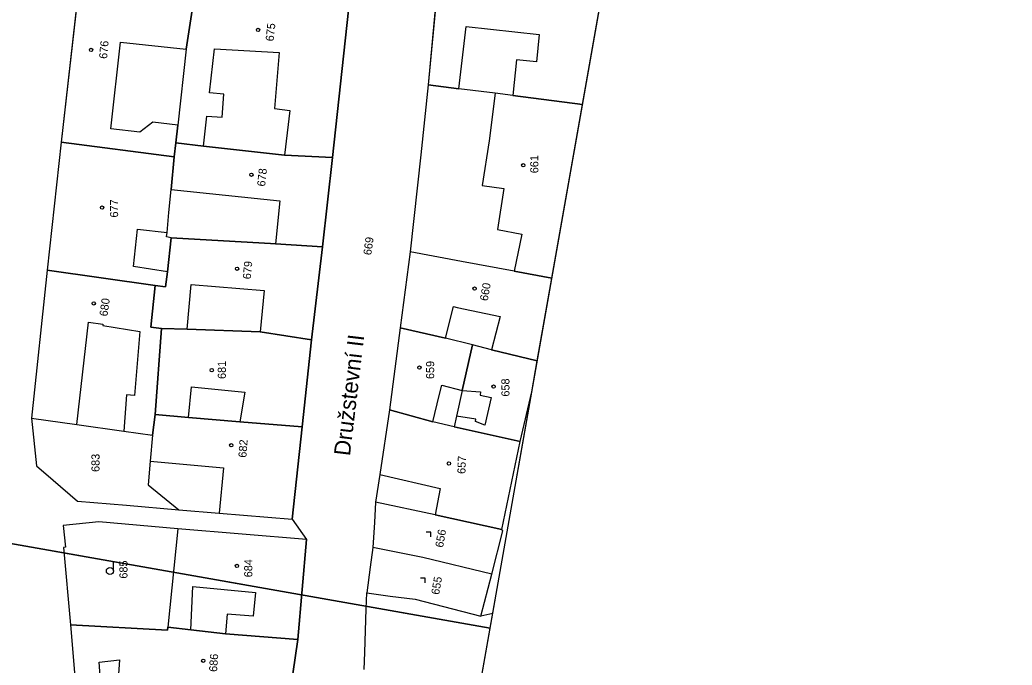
# Model space of a CAD drawing. Extents: x -534481 to -534262, y -1190577 to -1190138.
# Drawn here: x -534365.7 to -534261.7, y -1190477.6 to -1190410 of the extents above; entities that cross this region are included whole.
import ezdxf

# ---------------------------------------------------------------- set-up
doc = ezdxf.new("R2010")
doc.units = 0
for name, color, linetype in [('Definiční body', 7, 'Continuous'), ('Polygon budovy', 7, 'Continuous'), ('Polygon parcely', 7, 'Continuous'), ('Vrstva 30', 7, 'Continuous'), ('Vrstva 43', 7, 'Continuous'), ('Vrstva 46', 7, 'Continuous'), ('Vrstva 47', 7, 'Continuous'), ('Vrstva 48', 7, 'Continuous')]:
    doc.layers.add(name, color=color, linetype=linetype)

msp = doc.modelspace()

# ---------------------------------------------------------------- linework, layer by layer
at = {"layer": 'Definiční body'}
for p, q in [((-534321.81, -1190405.38), (-534322.86, -1190416.77)), ((-534359.48, -1190406.45), (-534361.32, -1190422.75)), ((-534331.23, -1190408.93), (-534332.91, -1190424.36)), ((-534361.32, -1190422.75), (-534362.8, -1190436.16)), ((-534361.32, -1190422.75), (-534349.49, -1190424.31)), ((-534349.49, -1190424.31), (-534349.31, -1190422.85)), ((-534332.91, -1190424.36), (-534333.96, -1190433.74)), ((-534333.96, -1190433.74), (-534335.08, -1190443.48)), ((-534324.75, -1190434.26), (-534325.81, -1190442.2)), ((-534362.8, -1190436.16), (-534364.44, -1190451.69)), ((-534362.8, -1190436.16), (-534351.49, -1190437.77)), ((-534351.49, -1190451.29), (-534350.82, -1190442.28)), ((-534325.81, -1190442.2), (-534326.91, -1190450.79)), ((-534335.08, -1190443.48), (-534336.06, -1190452.6)), ((-534313.23, -1190454.11), (-534312, -1190448.93)), ((-534351.77, -1190453.45), (-534351.49, -1190451.29)), ((-534336.06, -1190452.6), (-534337.13, -1190462.26)), ((-534313.23, -1190454.11), (-534320.15, -1190452.59)), ((-534351.77, -1190453.45), (-534351.99, -1190456.19)), ((-534315.15, -1190463.36), (-534313.23, -1190454.11)), ((-534337.13, -1190462.26), (-534335.61, -1190464.4)), ((-534349.11, -1190463.29), (-534350.15, -1190473.56)), ((-534335.61, -1190464.4), (-534349.11, -1190463.29)), ((-534335.61, -1190464.4), (-534336.54, -1190474.87)), ((-534317.36, -1190472.42), (-534316.19, -1190468.02)), ((-534360.35, -1190473.34), (-534359.92, -1190478.31))]:
    msp.add_line(p, q, dxfattribs=at)
for points in [[(-534347.45, -1190408.02), (-534348.24, -1190413.03), (-534349.11, -1190420.99), (-534349.31, -1190422.85)], [(-534322.86, -1190416.77), (-534323.65, -1190424.09), (-534324.75, -1190434.26)], [(-534306.7, -1190418.82), (-534314.01, -1190417.87), (-534315.84, -1190417.64), (-534319.66, -1190417.17), (-534322.86, -1190416.77)], [(-534349.31, -1190422.85), (-534346.43, -1190423.17), (-534337.91, -1190424.11), (-534332.91, -1190424.36)], [(-534349.79, -1190432.77), (-534350.28, -1190432.67), (-534350.24, -1190432.22), (-534350.04, -1190430.15), (-534349.82, -1190427.74), (-534349.49, -1190424.31)], [(-534351.49, -1190437.77), (-534350.38, -1190437.91), (-534350.2, -1190436.34), (-534349.79, -1190432.77)], [(-534349.79, -1190432.77), (-534345.53, -1190433.02), (-534339.38, -1190433.37), (-534338.88, -1190433.41), (-534333.96, -1190433.74)], [(-534309.9, -1190437), (-534313.86, -1190436.27), (-534319.38, -1190435.25), (-534324.75, -1190434.26)], [(-534351.49, -1190437.77), (-534351.94, -1190442.14), (-534350.82, -1190442.28)], [(-534350.82, -1190442.28), (-534348.14, -1190442.37), (-534340.49, -1190442.65), (-534335.08, -1190443.48)], [(-534318.21, -1190444.01), (-534321.04, -1190443.31), (-534325.81, -1190442.2)], [(-534318.21, -1190444.01), (-534319.29, -1190448.78), (-534319.9, -1190451.46), (-534320.15, -1190452.59)], [(-534311.43, -1190445.66), (-534316.23, -1190444.51), (-534318.21, -1190444.01)], [(-534326.91, -1190450.79), (-534327.94, -1190457.58), (-534328.38, -1190460.47)], [(-534320.15, -1190452.59), (-534322.37, -1190452.05), (-534326.91, -1190450.79)], [(-534364.44, -1190451.69), (-534363.92, -1190456.68), (-534362.18, -1190458.17), (-534359.62, -1190460.37), (-534354.49, -1190460.81), (-534349.01, -1190461.28)], [(-534364.44, -1190451.69), (-534359.68, -1190452.35), (-534354.78, -1190453.03), (-534351.77, -1190453.45)], [(-534351.49, -1190451.29), (-534348, -1190451.6), (-534342.6, -1190452.08), (-534336.06, -1190452.6)], [(-534351.99, -1190456.19), (-534352.2, -1190458.68), (-534349.01, -1190461.28)], [(-534349.01, -1190461.28), (-534344.78, -1190461.63), (-534337.13, -1190462.26)], [(-534328.38, -1190460.47), (-534328.51, -1190462.62), (-534328.68, -1190465.22)], [(-534315.15, -1190463.36), (-534322.12, -1190461.79), (-534328.38, -1190460.47)], [(-534349.11, -1190463.29), (-534357.38, -1190462.53), (-534361.12, -1190462.94), (-534360.89, -1190465.2), (-534361.07, -1190465.23), (-534360.35, -1190473.34)], [(-534316.19, -1190468.02), (-534315.05, -1190463.47), (-534315.15, -1190463.36)], [(-534328.68, -1190465.22), (-534328.95, -1190467.29), (-534329.3, -1190469.99)], [(-534316.19, -1190468.02), (-534323.42, -1190466.26), (-534328.68, -1190465.22)], [(-534329.58, -1190478.02), (-534329.52, -1190476.22), (-534329.36, -1190471.67), (-534329.3, -1190469.99)], [(-534329.3, -1190469.99), (-534326.86, -1190470.31), (-534324.23, -1190470.65), (-534317.36, -1190472.42)], [(-534316.1, -1190472.16), (-534317.36, -1190472.42)], [(-534360.35, -1190473.34), (-534350.19, -1190473.9), (-534350.15, -1190473.56)], [(-534350.15, -1190473.56), (-534347.75, -1190473.84), (-534344.1, -1190474.27), (-534336.54, -1190474.87)], [(-534336.54, -1190474.87), (-534337.79, -1190483.49), (-534339.53, -1190483.31)]]:
    msp.add_lwpolyline(points, dxfattribs=at)
at = {"layer": 'Polygon parcely'}
for p, q in [((-534306.7, -1190418.82), (-534304.95, -1190408.92)), ((-534309.9, -1190437), (-534306.7, -1190418.82)), ((-534311.43, -1190445.66), (-534309.9, -1190437)), ((-534312, -1190448.93), (-534311.43, -1190445.66))]:
    msp.add_line(p, q, dxfattribs=at)
for points in [[(-534304.95, -1190408.92), (-534304.7, -1190406.9), (-534310.69, -1190406.47), (-534319.12, -1190405.49), (-534321.81, -1190405.38), (-534322.86, -1190416.77), (-534319.66, -1190417.17), (-534318.89, -1190410.64), (-534311.23, -1190411.47), (-534311.53, -1190414.36), (-534313.6, -1190414.13), (-534314.01, -1190417.87), (-534306.7, -1190418.82)], [(-534306.7, -1190418.82), (-534314.01, -1190417.87), (-534315.84, -1190417.64), (-534316.47, -1190422.62), (-534317.22, -1190427.29), (-534314.94, -1190427.61), (-534315.59, -1190431.92), (-534313.05, -1190432.39), (-534313.86, -1190436.27), (-534309.9, -1190437)], [(-534309.9, -1190437), (-534313.86, -1190436.27), (-534319.38, -1190435.25), (-534324.75, -1190434.26), (-534325.81, -1190442.2), (-534321.04, -1190443.31), (-534320.22, -1190439.99), (-534319.82, -1190440.07), (-534315.33, -1190441.03), (-534316.23, -1190444.51), (-534311.43, -1190445.66)], [(-534311.43, -1190445.66), (-534316.23, -1190444.51), (-534318.21, -1190444.01), (-534319.29, -1190448.78), (-534317.38, -1190448.92), (-534317.43, -1190449.28), (-534316.26, -1190449.52), (-534316.94, -1190452.43), (-534317.91, -1190452.03), (-534317.88, -1190451.8), (-534319.9, -1190451.46), (-534320.15, -1190452.59), (-534313.23, -1190454.11), (-534312, -1190448.93)]]:
    msp.add_lwpolyline(points, dxfattribs=at)
for points in [[(-534350.73, -1190407.46), (-534351.28, -1190407.37), (-534359.48, -1190406.45), (-534361.32, -1190422.75), (-534349.49, -1190424.31), (-534349.31, -1190422.85), (-534349.11, -1190420.99), (-534351.71, -1190420.68), (-534353.09, -1190421.73), (-534356.12, -1190421.36), (-534355.1, -1190412.3), (-534348.24, -1190413.03), (-534347.45, -1190408.02)], [(-534349.31, -1190422.85), (-534346.43, -1190423.17), (-534346.07, -1190420.03), (-534344.47, -1190420.16), (-534344.27, -1190417.73), (-534345.78, -1190417.61), (-534345.25, -1190412.99), (-534338.47, -1190413.36), (-534338.99, -1190419.24), (-534337.36, -1190419.45), (-534337.91, -1190424.11), (-534332.91, -1190424.36), (-534331.23, -1190408.93), (-534336.56, -1190408.56), (-534340.34, -1190408.33), (-534347.45, -1190408.02), (-534348.24, -1190413.03), (-534349.11, -1190420.99)], [(-534353.76, -1190435.78), (-534353.33, -1190431.87), (-534350.24, -1190432.22), (-534350.04, -1190430.15), (-534349.82, -1190427.74), (-534349.49, -1190424.31), (-534361.32, -1190422.75), (-534362.8, -1190436.16), (-534351.49, -1190437.77), (-534350.38, -1190437.91), (-534350.2, -1190436.34)], [(-534349.82, -1190427.74), (-534338.42, -1190428.92), (-534338.88, -1190433.41), (-534333.96, -1190433.74), (-534332.91, -1190424.36), (-534337.91, -1190424.11), (-534346.43, -1190423.17), (-534349.31, -1190422.85), (-534349.49, -1190424.31)], [(-534338.88, -1190433.41), (-534339.38, -1190433.37), (-534345.53, -1190433.02), (-534349.79, -1190432.77), (-534350.2, -1190436.34), (-534350.38, -1190437.91), (-534351.49, -1190437.77), (-534351.94, -1190442.14), (-534350.82, -1190442.28), (-534348.14, -1190442.37), (-534347.71, -1190437.68), (-534340.05, -1190438.3), (-534340.49, -1190442.65), (-534335.08, -1190443.48), (-534333.96, -1190433.74)], [(-534356.98, -1190441.98), (-534353.08, -1190442.61), (-534353.66, -1190449.31), (-534354.47, -1190449.22), (-534354.78, -1190453.03), (-534351.77, -1190453.45), (-534351.49, -1190451.29), (-534350.82, -1190442.28), (-534351.94, -1190442.14), (-534351.49, -1190437.77), (-534362.8, -1190436.16), (-534364.44, -1190451.69), (-534359.68, -1190452.35), (-534358.48, -1190441.61), (-534356.98, -1190441.84)], [(-534348.14, -1190442.37), (-534350.82, -1190442.28), (-534351.49, -1190451.29), (-534348, -1190451.6), (-534347.67, -1190448.41), (-534342.08, -1190448.94), (-534342.6, -1190452.08), (-534336.06, -1190452.6), (-534335.08, -1190443.48), (-534340.49, -1190442.65)], [(-534326.91, -1190450.79), (-534322.37, -1190452.05), (-534321.7, -1190449.32), (-534321.43, -1190448.22), (-534319.29, -1190448.78), (-534318.21, -1190444.01), (-534321.04, -1190443.31), (-534325.81, -1190442.2)], [(-534327.94, -1190457.58), (-534321.62, -1190459.05), (-534322.12, -1190461.79), (-534315.15, -1190463.36), (-534313.23, -1190454.11), (-534320.15, -1190452.59), (-534322.37, -1190452.05), (-534326.91, -1190450.79)], [(-534344.78, -1190461.63), (-534337.13, -1190462.26), (-534336.06, -1190452.6), (-534342.6, -1190452.08), (-534348, -1190451.6), (-534351.49, -1190451.29), (-534351.77, -1190453.45), (-534351.99, -1190456.19), (-534344.31, -1190456.87)], [(-534341.2, -1190472.43), (-534343.94, -1190472.2), (-534344.1, -1190474.27), (-534336.54, -1190474.87), (-534335.61, -1190464.4), (-534349.11, -1190463.29), (-534350.15, -1190473.56), (-534347.75, -1190473.84), (-534347.55, -1190469.33), (-534340.96, -1190469.95)], [(-534360.35, -1190473.34), (-534359.92, -1190478.31), (-534359.56, -1190481.78), (-534357.01, -1190481.97), (-534357.36, -1190477.25), (-534355.22, -1190476.99), (-534355.37, -1190478.98), (-534346.45, -1190479.65), (-534346.59, -1190482.73), (-534339.53, -1190483.31), (-534337.79, -1190483.49), (-534336.54, -1190474.87), (-534344.1, -1190474.27), (-534347.75, -1190473.84), (-534350.15, -1190473.56), (-534350.19, -1190473.9)]]:
    msp.add_lwpolyline(points, close=True, dxfattribs=at)
at = {"layer": 'Vrstva 30'}
for q in [(-534298.13, -1190370.27), (-534462.61, -1190447.89)]:
    msp.add_line((-534316.37, -1190473.68), q, dxfattribs=at)
for points in [[(-534407.91, -1190137.67), (-534480.84, -1190551.29), (-534334.6, -1190577.08), (-534261.67, -1190163.46)], [(-534298.13, -1190370.27), (-534444.38, -1190344.48), (-534462.61, -1190447.89), (-534316.37, -1190473.68)], [(-534480.84, -1190551.29), (-534334.6, -1190577.08), (-534316.37, -1190473.68)]]:
    msp.add_lwpolyline(points, dxfattribs=at)
at = {"layer": 'Vrstva 43'}
msp.add_line((-534319.32, -1190473.15), (-534316.37, -1190473.68), dxfattribs=at)
msp.add_lwpolyline([(-534480.84, -1190551.29), (-534334.6, -1190577.08), (-534261.67, -1190163.46)], dxfattribs=at)
at = {"layer": 'Vrstva 46'}
for centre in [(-534340.69, -1190411.01), (-534358.2, -1190413.1), (-534312.9, -1190425.18), (-534341.39, -1190426.18), (-534357.04, -1190429.62), (-534342.9, -1190436.03), (-534318, -1190438.11), (-534357.91, -1190439.66), (-534345.55, -1190446.65), (-534323.79, -1190446.38), (-534316.01, -1190448.37), (-534343.5, -1190454.51), (-534320.7, -1190456.43), (-534342.92, -1190467.16), (-534346.44, -1190477.1)]:
    msp.add_circle(centre, 0.175, dxfattribs=at)
at = {"layer": 'Vrstva 48'}
for p, q in [((-534322.59, -1190463.61), (-534323.09, -1190463.61)), ((-534322.59, -1190464.11), (-534322.59, -1190463.61)), ((-534355.84, -1190467.69), (-534355.84, -1190466.81)), ((-534323.17, -1190468.43), (-534323.67, -1190468.43)), ((-534323.17, -1190468.93), (-534323.17, -1190468.43))]:
    msp.add_line(p, q, dxfattribs=at)
msp.add_circle((-534356.22, -1190467.69), 0.375, dxfattribs=at)

# ---------------------------------------------------------------- texts
at = {"layer": 'Polygon budovy'}
for s, rotation, p in [('675', 84, (-534339.07, -1190412.23)), ('676', 85, (-534356.52, -1190414.06)), ('661', 90, (-534311.32, -1190426.02)), ('678', 84, (-534339.96, -1190427.44)), ('677', 90, (-534355.36, -1190430.66)), ('669', 82, (-534328.84, -1190434.64)), ('679', 85, (-534341.46, -1190437.15)), ('660', 80, (-534316.63, -1190439.45)), ('680', 82, (-534356.49, -1190441.05)), ('681', 90, (-534344.07, -1190447.57)), ('659', 90, (-534322.24, -1190447.58)), ('658', 90, (-534314.35, -1190449.42)), ('682', 86, (-534341.92, -1190455.84)), ('683', 90, (-534357.31, -1190457.31)), ('657', 88, (-534318.97, -1190457.53)), ('656', 80, (-534321.31, -1190465.28)), ('685', 90, (-534354.38, -1190468.49)), ('684', 90, (-534341.3, -1190468.35)), ('655', 80, (-534321.73, -1190470.22)), ('686', 86, (-534345, -1190478.28))]:
    msp.add_text(s, height=0.85, rotation=rotation, dxfattribs=at).set_placement(p)
at = {"layer": 'Vrstva 47'}
msp.add_text('Družstevní II', height=1.7, rotation=83.2137, dxfattribs=at).set_placement((-534331.07, -1190455.69))

doc.saveas('drawing.dxf')
